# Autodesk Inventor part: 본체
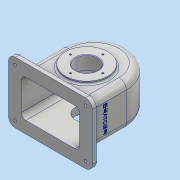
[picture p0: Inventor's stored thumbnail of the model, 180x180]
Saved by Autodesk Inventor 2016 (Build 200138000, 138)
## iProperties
Created: 2018-11
Part Number: 본체
Material: 알루미늄 6061
Document SubType Name: Modeling
Designer: user
Density: 2.7 g/cm^3
Appearance: 알루미늄 - 평지
Mass: 1091.74 g
Surface Area: 1182.04 cm^2
Volume: 404.349 cm^3
Author: user
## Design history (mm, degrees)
sketch "스케치1"
  geometry: L1 (-75, 55)-(75, 55); L2 (75, 55)-(75, -55); L3 (75, -55)-(-75, -55); L4 (-75, -55)-(-75, 55); L5 (-75, 55)-(75, -55); L6 (75, 55)-(-75, -55); 1 further point
  constraints: 12 end point, 2 midpoint, 2 parallel, 1 horizontal, 1 perpendicular
  dimensions: "d0" = 150 distance of L2.end L3.end; "d1" = 110 distance of L1.end L2.end
extrude "돌출1" new body sketch "스케치1" distance "d2" = 10; taper "d3" = 0 deg
node "작업 평면1"
sketch "스케치2"
  geometry: L1 (0, 10)-(150, 10) reference; L2 (133, 10)-(133, 78); L3 (17, 10)-(17, 78); L4 (150, 0)-(0, 0) reference; A1 r 58 centre (75, 78) between (133, 78) and (17, 78); 2 further points
  constraints: 4 end point, 2 horizontal alignment, 2 point on circle, 2 point on line, 2 vertical, 1 centre point, 1 midpoint, 1 vertical alignment
  dimensions: "d5" = 78 distance from line of L2.end L4; "d6" = 58 radius of A1
extrude "돌출2" join sketch "스케치2" distance "d7" = 77; taper "d8" = 0 deg
feature "쉘3" dims "d23" = 10, "d24" = 6, "d25" = 5
sketch "스케치3"
  geometry: L1 (-150, 10)-(0, 10) reference; L2 (0, 0)-(-150, 0) reference; C1 r 38 at (-75, 65); 2 further points
  constraints: 1 centre point, 1 midpoint, 1 vertical alignment
  dimensions: "d11" = 76 diameter of C1; "d12" = 65 distance from line of L2 C1.centre
extrude "돌출3" join sketch "스케치3" distance "d13" = 5; taper "d14" = 0 deg
sketch "스케치4"
  geometry: L1 (0, 10)-(150, 10) reference; L2 (150, 0)-(0, 0) reference; C1 r 38 at (75, 65); 2 further points
  constraints: 1 centre point, 1 midpoint, 1 vertical alignment
  dimensions: "d15" = 76 diameter of C1; "d16" = 65 distance from line of L2 C1.centre
extrude "돌출4" join sketch "스케치4" distance "d17" = 10; taper "d18" = 0 deg
sketch "스케치5"
  geometry: L1 (-75, -78)-(75, -78) reference; L2 (-58, -68)-(58, -68) reference; C1 r 28 at (0, -13); 2 further points
  constraints: 1 centre point, 1 midpoint, 1 vertical alignment
  dimensions: "d26" = 56 diameter of C1; "d27" = 65 distance from line of C1.centre L1
extrude "돌출5" join sketch "스케치5" distance "d28" = 14; taper "d29" = 0 deg
feature "면 기울기1" dims angle "d30" = 40 deg
sketch "스케치6"
  geometry: C1 r 20 at (0, 0); C2 r 38 at (0, 0) reference; 1 further point
  constraints: 1 centre point, 1 concentric
  dimensions: "d31" = 40 diameter of C1
extrude "돌출6" cut sketch "스케치6" stored distance "d32" = 14; taper "d33" = 0 deg
node "작업 평면2"
sketch "스케치7"
  geometry: L1 (38, 43.5)-(-38, 43.5) reference; L2 (75, 55)-(75, -55) reference; C1 r 6 at (0, 0); 1 further point
  constraints: 1 centre point
  dimensions: "d35" = 12 diameter of C1; "d36" = 43.5 distance from line of C1.centre L1; "d37" = 75 distance from line of C1.centre L2
extrude "돌출7" join sketch "스케치7" stored distance "d38" = 10; taper "d39" = 0 deg
sketch "스케치8"
  geometry: C1 r 6 at (0, 0) reference; 1 further point
hole "구멍1" sketch "스케치8" at (0, 0) diameter "d42" = 4.459; stored, may be unused: countersink angle "d46" = 90 deg, drill point angle "d48" = 118 deg; dims "d43" = 100, "d44" = 4, "d45" = 2, "d47" = 12.8
sketch "스케치9" dims "d49" = 58
  geometry: C1 r 38 at (0, 0) reference; 3 further points
  constraints: 2 horizontal alignment, 3 other
hole "구멍2" sketch "스케치9" at (-29, 0) diameter "d50" = 3.242; stored, may be unused: countersink angle "d54" = 90 deg, drill point angle "d56" = 118 deg; dims "d51" = 8, "d52" = 4, "d53" = 2, "d55" = 10
sketch "스케치10" dims "d60" = 58
  geometry: C1 r 20 at (0, 0) reference; 3 further points
  constraints: 2 horizontal alignment, 3 other
hole "구멍3" sketch "스케치10" at (-29, 0) diameter "d61" = 3.242; stored, may be unused: countersink angle "d65" = 90 deg, drill point angle "d67" = 118 deg; dims "d62" = 8, "d63" = 4, "d64" = 2, "d66" = 10
fillet "모깎기1" dims "d71" = 12
sketch "스케치11"
  geometry: A1 r 12 centre (-63, 43) between (-63, 55) and (-75, 43) reference; A2 r 12 centre (63, 43) between (75, 43) and (63, 55) reference; A3 r 12 centre (63, -43) between (63, -55) and (75, -43) reference; A4 r 12 centre (-63, -43) between (-75, -43) and (-63, -55) reference; 1 further point
hole "구멍4" sketch "스케치11" at (-63, -43), (63, -43), (63, 43), (-63, 43) diameter "d72" = 12; stored, may be unused: countersink angle "d76" = 90 deg, drill point angle "d78" = 0 deg; dims "d73" = 8, "d74" = 4, "d75" = 2, "d77" = 4
sketch "스케치12"
  geometry: C1 r 6 at (-63, 43) reference; C2 r 6 at (63, 43) reference; C3 r 6 at (-63, -43) reference; C4 r 6 at (63, -43) reference; 1 further point
hole "구멍5" sketch "스케치12" at (-63, 43), (-63, -43), (63, -43), (63, 43) diameter "d79" = 5; stored, may be unused: countersink angle "d83" = 90 deg, drill point angle "d85" = 0 deg; dims "d80" = 8, "d81" = 4, "d82" = 2, "d84" = 4
fillet "모깎기2" dims "d86" = 13
fillet "모깎기3" dims "d87" = 8
fillet "모깎기4" dims "d88" = 3
chamfer "모따기1" distance "d89" = 1; stored, may be unused: second distance "d90" = 2, angle "d91" = 45 deg
sketch "스케치13"
  geometry: L1 (68.5, -78)-(-17.5, -78) reference; L2 (-13, 0)-(-13, -65) reference; 2 further points
  constraints: 1 other
  dimensions: "d93" = 40 distance from line of L1 point (25.5, -38); "d94" = 38.5 distance from line of point (25.5, -38) L2
feature "엠보싱1" sketch "스케치13" dims "d0" = 150, "d1" = 110, "d95" = 0.5, "d96" = 0
feature "면 기울기3" dims angle "d97" = 5 deg
fillet "모깎기6" dims "d98" = 3
node "솔리드1"
pattern_circular "원형 패턴1" dims angle "d58" = 360 deg
pattern_circular "원형 패턴2" dims angle "d69" = 360 deg
node "투영된 루프1"
node "투영된 루프2"
node "투영된 루프3"
other parameters: "d4" = -93.5, "d34" = -142
